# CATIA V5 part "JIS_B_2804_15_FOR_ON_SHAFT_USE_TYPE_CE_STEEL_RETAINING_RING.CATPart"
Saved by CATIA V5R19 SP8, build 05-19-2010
Part number: JIS B 2804 RING 15 STEEL RETAINING FOR ON SHAFT USE TYPE CE
Nomenclature: 39_b
Bounding box of the stored display mesh (mm): x 0 to 1, y -8.473 to 8.473, z -10.35 to 9
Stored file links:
  C:\Users\rphgr\Desktop\0_Tapis_TC520B_vitesse\JIS_B_2804_15_FOR_ON_SHAFT_USE_TYPE_CE_STEEL_RETAINING_RING.CATPart
  C:\Mechanical_Catalogue\JIS_Standards\Models\JIS_B_2804_RETAINING_RING_FOR_ON_SHAFT_USE_TYPE_CE_a.CATPart
  C:\Program Files\Dassault Systemes\B19\win_b64\startup\components\MechanicalStandardParts\JIS_Standards\Design_Tables\JIS_B_2804_RETAINING_RING_FOR_ON_SHAFT_USE_TYPE_CE.txt
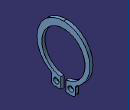
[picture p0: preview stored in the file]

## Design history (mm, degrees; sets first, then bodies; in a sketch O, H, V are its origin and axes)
Parameters
  a_cutend = 3.5 mm
  do_hole_dia = 1.7 mm
  d3_basic_dia = 13.8 mm
  b_width = 2.1 mm
  d4_dia = 16.95 mm
  t_thickness_basic = 1 mm
  Designation = 25
Body1 (main body)
  Sketch1 on yz-plane, origin (0, 0, 0), H (0, 1, 0), V (0, 0, 1)
    point P1 (0, 0.525)
    line L1 (0.83, -10.3499) -> (2.955, -10.3499)
    point P3 (0.83, -6.8499)
    arc A1 centre (0, 0) radius 6.9 from (0.83, -6.8499) to (0, 6.9) ccw
    line L2 (0.83, -6.8499) -> (0.83, -10.3499)
    reference intersected line E1 through (0, -1000000) direction (0, 1)
    line L3 (3.805, -7.555) -> (3.805, -9.4999)
    point P4 (0, 6.9)
    point P5 (0, 9)
    arc A2 centre (0, 0.525) radius 8.475 from (4.2307, -6.8185) to (0, 9) ccw
    arc A3 centre (4.655, -7.555) radius 0.85 from (4.2307, -6.8185) to (3.805, -7.555) ccw
    point P6 (4.2307, -6.8185)
    point P7 (3.805, -7.555)
    arc A4 centre (2.955, -9.4999) radius 0.85 from (3.805, -9.4999) to (2.955, -10.3499) cw
    point P9 (3.805, -9.4999)
    point P10 (2.955, -10.3499)
    point P12 (-2.955, -10.3499)
    point P13 (-3.805, -9.4999)
    arc A5 centre (-2.955, -9.4999) radius 0.85 from (-3.805, -9.4999) to (-2.955, -10.3499) ccw
    point P15 (-3.805, -7.555)
    point P16 (-4.2307, -6.8185)
    arc A6 centre (-4.655, -7.555) radius 0.85 from (-4.2307, -6.8185) to (-3.805, -7.555) cw
    point P18 (0, 9)
    arc A7 centre (0, 0.525) radius 8.475 from (-4.2307, -6.8185) to (0, 9) cw
    line L4 (-3.805, -7.555) -> (-3.805, -9.4999)
    point P21 (-0.83, -6.8499)
    line L5 (-0.83, -6.8499) -> (-0.83, -10.3499)
    point P22 (0, 6.9)
    arc A8 centre (0, 0) radius 6.9 from (-0.83, -6.8499) to (0, 6.9) cw
    line L6 (-0.83, -10.3499) -> (-2.955, -10.3499)
    distance L2 E1 = 0.83
    distance L2 L3 = 2.975 {= a_cutend *0.85}
    radius A2 = 8.475 {= d4_dia /2}
    distance P4 P5 = 2.1 {= b_width}
    radius A1 = 6.9 {= d3_basic_dia /2}
    radius A3 = 0.85 {= do_hole_dia /2}
    distance L1 P3 = 3.5 {= a_cutend}
    radius A4 = 0.85 {= Sketch1.radius(A3)}
    coincidence: P1 V, V P4, P5 V, P4 P22, P5 P18
    horizontal: L1 H
    tangency: A3 A2, A3 L3, A4 L3, A4 L1
    symmetry: A4 A5 V, A3 A6 V, A2 A7 V, L3 L4 V, L2 L5 V, A1 A8 V, L1 L6 V, P10 P12 V, P9 P13 V, P7 P15 V, P6 P16 V, P5 P18 V, P4 P22 V, P3 P21 V
  Pad1: profile Sketch1, direction (1, 0, 0), length 1 {= t_thickness_basic}
  Body2
    Sketch2 on yz-plane, origin (0, 0, 0), H (0, 1, 0), V (0, 0, 1)
      point P1 (2.3175, -8.6499)
      circle A1 centre (2.3175, -8.6499) radius 0.85
      reference projected line E3 (0.83, -56.463) -> (0.83, -67.363)
      reference projected line E4 (6.525, -61.9955) -> (6.525, -65.863)
      axis line L1 (0, -3.9796) -> (0, -23.6479)
      point P2 (0, -3.9796)
      circle A2 centre (-2.3175, -8.6499) radius 0.85
      reference projected line E5 (0.83, -10.3499) -> (0.83, -6.8499) from edge of Pad1
      reference projected line E6 (2.955, -10.3499) -> (0.83, -10.3499) from edge of Pad1
      radius A1 = 0.85 {= do_hole_dia /2}
      distance E3 E4 = 5.695
      distance E5 P1 = 1.4875 {= a_cutend *.85/2}
      distance P1 E6 = 1.7 {= do_hole_dia}
      coincidence: P2 V
      vertical: L1 V
      symmetry: A1 A2 L1
    Pad2: profile Sketch2, direction (1, 0, 0), length 1 {= t_thickness_basic}
  Remove1: tool Body2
